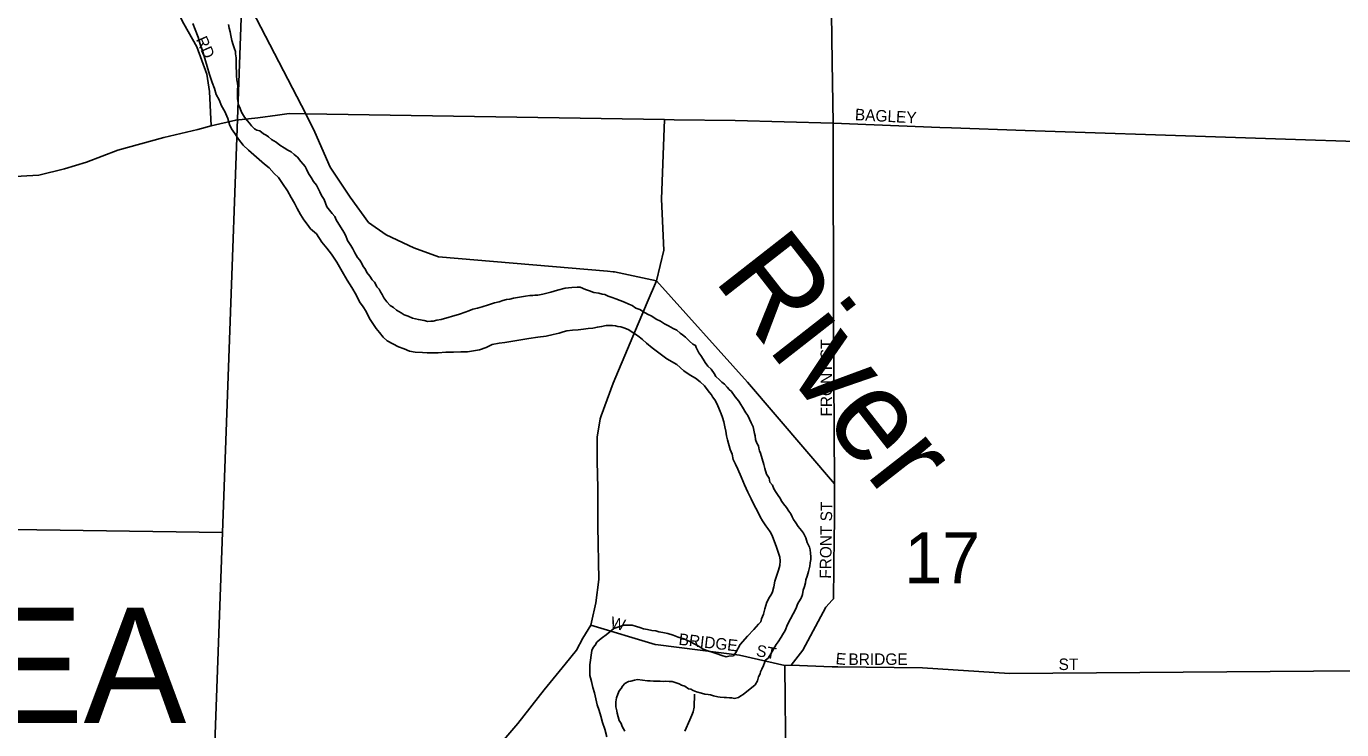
# Model space of a CAD drawing. Extents: x 2010165 to 2382125, y 1060529 to 1407316.
# Drawn here: x 2142658 to 2148360, y 1226696 to 1229747 of the extents above; entities that cross this region are included whole.
import ezdxf

# ---------------------------------------------------------------- set-up
doc = ezdxf.new("R2010")
doc.units = 0
for name, color, linetype in [('GM_X_City_Street', 7, 'Continuous'), ('GM_X_City_Street_Text', 7, 'Continuous'), ('GM_X_Corporation_Text', 7, 'Continuous'), ('GM_X_Major_River', 7, 'Continuous'), ('GM_X_Major_River_Text', 7, 'Continuous'), ('GM_X_Minor_River', 7, 'Continuous'), ('GM_X_Section', 7, 'Continuous'), ('GM_X_Section_Text', 7, 'Continuous'), ('GM_X_State_Route', 7, 'Continuous')]:
    doc.layers.add(name, color=color, linetype=linetype)

msp = doc.modelspace()

# ---------------------------------------------------------------- linework, layer by layer
at = {"layer": 'GM_X_City_Street'}
for points in [[(2143869.2, 1229367.1), (2143460.8, 1230156), (2143301.8, 1230460.3), (2143187.6, 1230770.6), (2143171.3, 1230819.6), (2143165.9, 1230857.7), (2143171.3, 1230890.4), (2143171.3, 1230923), (2143204, 1230966.6), (2143274.8, 1231053.7), (2143911.8, 1231538), (2144293.9, 1231811), (2144500.5, 1231991.2), (2144574.7, 1232072.4), (2144945.5, 1232809), (2146080.9, 1235222.3)], [(2143459.7, 1229315.1), (2143452.4, 1229463.5), (2143439.8, 1229539.5), (2143396.8, 1229657.5), (2143339.9, 1229757.3), (2143285, 1229865.1), (2143238.3, 1229946.9), (2143187.7, 1230020.6), (2143145.2, 1230076.3), (2143017.2, 1230237.5), (2142992.9, 1230257.7), (2142956.4, 1230290.2), (2142903.6, 1230330.8), (2142859, 1230387.6), (2142826.6, 1230432.3), (2142769.8, 1230497.1), (2142673.2, 1230622.5)], [(2141028.6, 1229111.9), (2141449.4, 1229107.7), (2142187.5, 1229094.6), (2142583.5, 1229094.3), (2142711.5, 1229101.5), (2142823.2, 1229128.6), (2142919, 1229157.6), (2143054.6, 1229209), (2143254.1, 1229265), (2143401.8, 1229298.5), (2143459.7, 1229315.1), (2143565.4, 1229340.1), (2143661.4, 1229349.1), (2143747.3, 1229361.9), (2143797.2, 1229368.4), (2143869.2, 1229367.1)], [(2145177.2, 1228684.1), (2144444.4, 1228746.6), (2144338.1, 1228785.7), (2144217.6, 1228842.8), (2144141.2, 1228896.2), (2144062.2, 1229005.8), (2143975.2, 1229135.4), (2143907.9, 1229287.2), (2143869.2, 1229367.1)], [(2143869.2, 1229367.1), (2145423.9, 1229342)], [(2146157.5, 1228440.3), (2146154.9, 1229326.2)], [(2146154.9, 1229326.2), (2146617.4, 1229308.6)], [(2146617.4, 1229308.6), (2146668.8, 1229306.7)], [(2146668.8, 1229306.7), (2146987.2, 1229294.6), (2148724.6, 1229237.6)], [(2145389.1, 1228642.7), (2145207, 1228681.6), (2145201.5, 1228682), (2145177.2, 1228684.1)], [(2146161.3, 1227703.8), (2146161.3, 1227762.9), (2145784.7, 1228202.8), (2145389.1, 1228642.7)], [(2146161.3, 1227762.9), (2146158.1, 1228228.1), (2146157.5, 1228440.3)], [(2146160.5, 1227536.1), (2146161.3, 1227592), (2146161.3, 1227703.8)], [(2146151.2, 1227258.7), (2146156.5, 1227264.5), (2146160.5, 1227536.1)], [(2145973, 1226976.5), (2146023.6, 1227041.4), (2146123.3, 1227228.1), (2146151.2, 1227258.7)], [(2145104.3, 1227149), (2145383.6, 1227065.5), (2145396.2, 1227063.9)], [(2145396.2, 1227063.9), (2145749.9, 1227019.2), (2145946.1, 1226974.9), (2145973, 1226976.5)], [(2146034.9, 1226118.8), (2146028.4, 1226153.7), (2145961.9, 1226419.5), (2145950.8, 1226538.2), (2145946.1, 1226974.9)], [(2145973, 1226976.5), (2146151.8, 1226968.6), (2146176.1, 1226968.3)], [(2146176.1, 1226968.3), (2146542.6, 1226963.9), (2146919.6, 1226940.5), (2148615.5, 1226952.3)]]:
    msp.add_lwpolyline(points, dxfattribs=at)
at = {"layer": 'GM_X_Major_River'}
for points in [[(2144026.4, 1228683.3), (2144003.8, 1228723.2), (2143981.3, 1228759), (2143960.9, 1228784.9), (2143938.6, 1228810.7), (2143916, 1228846.5), (2143889.7, 1228868.3), (2143875.4, 1228888.2), (2143861.2, 1228908.1), (2143846.8, 1228929.9), (2143832.5, 1228955.9), (2143820.1, 1228979.8), (2143805.8, 1229003.7), (2143789.4, 1229033.6), (2143768.9, 1229065.4), (2143750.6, 1229091.3), (2143732.3, 1229109.1), (2143709.9, 1229132.9), (2143689.7, 1229148.7), (2143620.8, 1229210.1), (2143598.4, 1229231.9), (2143578.1, 1229257.7), (2143561.7, 1229281.6), (2143547.4, 1229301.5), (2143539.2, 1229321.4), (2143530.8, 1229347.4), (2143518.4, 1229377.4), (2143504.1, 1229401.3), (2143493.7, 1229427.2), (2143481.4, 1229451.2), (2143473, 1229477.1), (2143462.7, 1229503.1), (2143452.2, 1229537.1), (2143441.7, 1229573.1), (2143431.3, 1229607.1), (2143420.8, 1229641), (2143410.3, 1229673), (2143402, 1229699), (2143389.5, 1229732.9), (2143379.2, 1229758.9)], [(2143533.5, 1229754.8), (2143537.7, 1229738.8), (2143541.9, 1229722.8), (2143544.1, 1229706.8), (2143548.4, 1229684.7), (2143554.7, 1229666.8), (2143560.9, 1229648.8), (2143565.1, 1229636.8), (2143565.2, 1229626.8), (2143567.4, 1229610.7), (2143567.7, 1229590.7), (2143567.8, 1229580.6), (2143568, 1229566.6), (2143568.2, 1229550.5), (2143568.5, 1229532.5), (2143570.7, 1229514.5), (2143572.9, 1229500.4), (2143575.1, 1229486.4), (2143573.3, 1229472.3), (2143573.4, 1229462.3), (2143573.6, 1229444.3), (2143573.8, 1229432.2), (2143578.1, 1229406.2), (2143584.4, 1229390.2), (2143590.6, 1229374.2), (2143602.9, 1229352.3), (2143615.1, 1229338.4), (2143625.3, 1229326.5), (2143633.4, 1229314.6), (2143647.6, 1229302.7), (2143657.7, 1229296.8), (2143669.8, 1229292.9), (2143686, 1229281.1), (2143698.1, 1229275.2), (2143708.2, 1229267.3), (2143720.4, 1229255.4), (2143740.5, 1229243.7), (2143756.7, 1229231.8), (2143774.9, 1229220), (2143791.1, 1229210.2), (2143805.2, 1229202.3), (2143819.4, 1229190.4), (2143833.6, 1229178.6), (2143847.8, 1229160.7), (2143858, 1229148.8), (2143866.1, 1229138.9), (2143872.3, 1229126.9), (2143880.6, 1229108.9), (2143892.8, 1229091), (2143903.1, 1229073.1), (2143915.3, 1229057.2), (2143923.5, 1229043.3), (2143929.7, 1229029.3), (2143937.9, 1229013.3), (2143948.2, 1228995.4), (2143960.6, 1228963.4), (2143983, 1228935.6), (2143995.2, 1228921.7), (2144001.4, 1228907.8), (2144034.2, 1228854), (2144042.4, 1228838), (2144050.7, 1228818.1), (2144065, 1228796.2), (2144073.2, 1228782.2), (2144081.4, 1228764.3), (2144093.7, 1228744.4), (2144103.9, 1228732.5), (2144112.1, 1228718.5), (2144118.3, 1228704.5), (2144126.4, 1228694.6), (2144134.6, 1228678.7), (2144146.9, 1228662.8), (2144157.1, 1228646.8), (2144167.2, 1228636.9), (2144173.4, 1228627), (2144177.5, 1228617), (2144187.7, 1228607.1), (2144193.8, 1228595.1)], [(2145923.9, 1227444.6), (2145909.3, 1227488.5), (2145890.6, 1227538.5), (2145882.4, 1227554.4), (2145872.2, 1227568.3), (2145864, 1227580.3), (2145849.7, 1227602.2), (2145839.5, 1227620.1), (2145827.1, 1227644), (2145812.8, 1227669.9), (2145800.4, 1227697.9), (2145786, 1227725.8), (2145771.6, 1227757.7), (2145757.1, 1227793.6), (2145742.6, 1227825.6), (2145732.3, 1227847.5), (2145722, 1227867.5), (2145717.7, 1227891.5), (2145709.4, 1227911.5), (2145696.9, 1227953.4), (2145692.6, 1227971.4), (2145690.4, 1227991.5), (2145686.1, 1228009.5), (2145681.8, 1228031.5), (2145675.6, 1228049.5), (2145669.4, 1228065.5), (2145663.1, 1228083.4), (2145652.8, 1228107.4), (2145642.5, 1228127.3), (2145632.3, 1228139.2), (2145628.2, 1228149.2), (2145620, 1228159.2), (2145609.9, 1228171.1), (2145597.6, 1228187), (2145579.4, 1228204.8), (2145559.1, 1228220.6), (2145534.9, 1228234.4), (2145508.6, 1228252.1), (2145478.2, 1228279.8), (2145433.8, 1228305.3), (2145399.4, 1228331), (2145371.1, 1228352.7), (2145346.8, 1228372.5), (2145328.5, 1228388.3), (2145314.4, 1228400.2), (2145298.2, 1228412), (2145284, 1228419.9), (2145269.9, 1228429.8), (2145251.8, 1228437.6), (2145235.7, 1228443.4), (2145221.6, 1228445.2), (2145211.6, 1228447.1), (2145199.5, 1228448.9), (2145187.5, 1228448.8), (2145171.5, 1228448.6), (2145151.5, 1228444.3), (2145133.5, 1228442.1), (2145113.5, 1228437.9), (2145093.5, 1228435.6), (2145073.5, 1228433.4), (2145049.5, 1228431.1), (2145025.5, 1228428.8), (2145001.5, 1228426.4), (2144985.5, 1228422.2), (2144967.5, 1228416), (2144941.6, 1228409.7), (2144911.6, 1228403.3), (2144875.6, 1228398.8), (2144835.6, 1228392.3), (2144731.7, 1228375), (2144707.6, 1228372.7), (2144677.7, 1228366.3), (2144651.8, 1228353.9), (2144621.9, 1228343.5), (2144595.9, 1228339.2), (2144569.9, 1228334.9), (2144541.8, 1228334.5), (2144509.8, 1228334.1), (2144475.7, 1228333.7), (2144443.7, 1228331.3), (2144417.7, 1228331), (2144395.6, 1228330.7), (2144375.6, 1228332.5), (2144343.5, 1228334.1), (2144319.4, 1228337.8), (2144295.2, 1228347.6), (2144271.1, 1228357.3), (2144246.9, 1228369), (2144222.7, 1228382.8), (2144204.4, 1228398.6), (2144188.1, 1228418.5), (2144173.9, 1228436.3), (2144159.6, 1228458.2), (2144145.2, 1228480.1), (2144130.8, 1228510.1), (2144118.5, 1228530), (2144102.2, 1228551.8), (2144087.8, 1228581.8), (2144069.4, 1228613.6), (2144048.9, 1228645.5), (2144026.4, 1228683.3)], [(2144193.8, 1228595.1), (2144200, 1228583.1), (2144208.2, 1228569.2), (2144220.5, 1228551.3), (2144234.7, 1228535.4), (2144248.8, 1228527.6), (2144263, 1228515.7), (2144283.2, 1228503.9), (2144295.3, 1228496), (2144313.4, 1228490.2), (2144331.6, 1228480.4), (2144357.7, 1228474.7), (2144381.8, 1228471), (2144397.9, 1228467.2), (2144411.9, 1228467.4), (2144421.9, 1228467.5), (2144437.9, 1228471.7), (2144455.8, 1228475.9), (2144535.7, 1228499), (2144559.6, 1228507.3), (2144575.6, 1228513.5), (2144593.5, 1228519.8), (2144613.5, 1228524), (2144633.5, 1228530.3), (2144661.4, 1228538.6), (2144687.3, 1228547), (2144707.3, 1228551.3), (2144723.3, 1228557.5), (2144739.2, 1228561.7), (2144753.2, 1228563.9), (2144769.2, 1228568.1), (2144795.2, 1228572.4), (2144821.2, 1228576.7), (2144841.2, 1228579), (2144853.2, 1228579.1), (2144863.2, 1228581.3), (2144875.2, 1228581.4), (2144897.2, 1228585.7), (2144931.1, 1228594.1), (2144961.1, 1228602.5), (2144993, 1228610.9), (2145023.1, 1228613.3), (2145045.1, 1228615.6), (2145059.1, 1228615.8), (2145081.2, 1228606), (2145099.4, 1228600.2), (2145117.5, 1228592.4), (2145139.6, 1228588.7), (2145153.7, 1228584.8), (2145165.7, 1228583), (2145179.8, 1228577.1), (2145197.9, 1228571.3), (2145214, 1228565.5), (2145232.2, 1228557.7), (2145250.3, 1228549.9), (2145270.4, 1228542.1), (2145284.5, 1228536.3), (2145300.7, 1228524.4), (2145316.8, 1228518.6), (2145333, 1228508.8), (2145351.1, 1228499), (2145369.3, 1228489.2), (2145387.5, 1228477.3), (2145407.6, 1228467.6), (2145423.8, 1228455.7), (2145442, 1228447.9), (2145452, 1228442), (2145462.1, 1228436.1), (2145478.3, 1228428.3), (2145492.5, 1228416.4), (2145502.6, 1228408.5), (2145514.7, 1228398.6), (2145533, 1228380.8), (2145547.2, 1228368.9), (2145559.3, 1228363.1), (2145561.4, 1228353.1), (2145573.7, 1228331.1), (2145581.9, 1228319.2), (2145592.1, 1228303.3), (2145600.3, 1228289.3), (2145612.5, 1228273.4), (2145626.7, 1228259.6), (2145639, 1228241.7), (2145647.2, 1228227.7), (2145663.4, 1228213.9), (2145673.5, 1228204), (2145683.7, 1228194.1), (2145695.9, 1228182.2), (2145704, 1228172.2), (2145714.2, 1228162.3), (2145730.5, 1228140.4), (2145746.8, 1228120.6), (2145755, 1228106.6), (2145763.1, 1228094.7), (2145777.5, 1228070.8), (2145785.6, 1228058.9), (2145800.1, 1228026.9), (2145808.3, 1228009), (2145814.7, 1227981), (2145816.8, 1227971), (2145819.1, 1227954.9)], [(2145819.1, 1227954.9), (2145825.3, 1227939), (2145831.5, 1227927), (2145833.6, 1227917), (2145835.8, 1227905), (2145839.9, 1227895), (2145854.5, 1227847), (2145858.8, 1227829), (2145867.1, 1227805), (2145877.4, 1227787.1), (2145881.6, 1227769.1), (2145891.8, 1227757.2), (2145898, 1227741.2), (2145908.2, 1227725.3), (2145916.4, 1227711.3), (2145924.6, 1227701.4), (2145932.8, 1227685.5), (2145940.9, 1227675.5), (2145953.2, 1227659.6), (2145963.4, 1227643.7), (2145971.6, 1227631.8), (2145977.7, 1227619.8), (2145983.9, 1227607.8), (2145994.1, 1227593.9), (2146004.3, 1227578), (2146018.6, 1227560.1), (2146026.8, 1227548.2), (2146037, 1227528.2), (2146043.3, 1227508.2), (2146053.6, 1227488.3), (2146055.7, 1227476.3), (2146057.9, 1227462.3), (2146058.1, 1227446.2), (2146058.3, 1227434.2), (2146056.5, 1227420.1), (2146054.7, 1227406.1), (2146050.8, 1227394), (2146049, 1227381.9), (2146043.2, 1227361.8), (2146037.4, 1227345.6), (2146035.6, 1227333.6), (2146031.8, 1227317.5), (2146026, 1227301.3), (2146022.2, 1227283.2), (2146016.4, 1227267.1), (2146006.6, 1227250.9), (2146000.7, 1227240.8), (2145994.9, 1227222.7), (2145957.8, 1227152), (2145948.1, 1227125.8), (2145936.3, 1227107.6), (2145930.5, 1227097.5), (2145916.7, 1227077.3), (2145908.9, 1227065.2), (2145897.1, 1227044.9), (2145885.3, 1227024.7), (2145873.6, 1227006.5), (2145861.6, 1226998.4), (2145853.9, 1226974.2), (2145846.1, 1226958.1), (2145840.3, 1226947.9), (2145838.4, 1226937.9), (2145832.5, 1226925.8), (2145826.8, 1226907.6), (2145817, 1226891.5), (2145765.4, 1226848.7), (2145755.5, 1226842.6), (2145745.6, 1226836.4), (2145727.6, 1226832.2), (2145715.5, 1226834), (2145705.5, 1226833.9), (2145693.5, 1226835.8), (2145683.5, 1226835.7), (2145665.4, 1226837.4), (2145655.4, 1226839.3), (2145637.3, 1226843.1), (2145623.2, 1226846.9), (2145613.2, 1226848.8), (2145599.1, 1226850.7), (2145585, 1226854.5), (2145562.9, 1226860.3), (2145548.8, 1226866.1), (2145538.7, 1226872), (2145528.7, 1226873.9), (2145512.5, 1226885.7), (2145498.4, 1226889.6), (2145488.3, 1226895.5), (2145470.2, 1226901.3), (2145458.2, 1226905.1), (2145444.1, 1226905), (2145430.1, 1226906.8), (2145418.1, 1226904.6), (2145406, 1226906.5), (2145392, 1226906.3), (2145376, 1226906.1), (2145361.9, 1226908), (2145349.9, 1226907.8), (2145307.8, 1226913.3), (2145293.8, 1226911.1), (2145277.8, 1226906.9), (2145267.8, 1226904.8)], [(2145174.8, 1226664.9), (2145166.3, 1226698.9), (2145156, 1226726.8), (2145147.6, 1226754.8), (2145141.2, 1226778.8), (2145132.9, 1226804.8), (2145126.5, 1226830.8), (2145120.2, 1226856.8), (2145113.9, 1226878.8), (2145107.5, 1226904.8), (2145103.3, 1226920.8), (2145101.2, 1226930.8), (2145101, 1226946.9), (2145100.6, 1226977), (2145109.8, 1227039.3), (2145115.6, 1227053.4), (2145123.5, 1227063.5), (2145131.3, 1227075.7), (2145143.2, 1227085.8), (2145155.1, 1227096), (2145171, 1227108.3), (2145186.9, 1227120.5), (2145204.7, 1227134.8), (2145230.6, 1227143.1), (2145248.6, 1227149.3), (2145262.6, 1227149.5), (2145274.6, 1227149.7), (2145284.6, 1227149.8), (2145302.8, 1227144), (2145316.8, 1227140.1), (2145332.9, 1227134.3), (2145351, 1227130.5), (2145369.1, 1227126.8), (2145387.2, 1227125), (2145399.2, 1227121.1), (2145417.3, 1227117.3), (2145439.4, 1227113.6), (2145461.5, 1227105.8), (2145483.7, 1227098.1), (2145507.8, 1227090.3), (2145534, 1227078.6), (2145556.2, 1227066.8), (2145572.3, 1227059), (2145582.4, 1227053.1), (2145592.6, 1227045.2), (2145616.7, 1227037.5), (2145634.8, 1227031.7), (2145652.9, 1227025.9), (2145673.1, 1227018.1), (2145691.2, 1227012.3), (2145703.2, 1227014.5), (2145723.2, 1227016.7), (2145733, 1227030.9), (2145752.6, 1227065.2), (2145784.2, 1227101.8), (2145811.8, 1227130.2), (2145831.6, 1227154.5), (2145841.4, 1227164.6), (2145845.3, 1227176.7), (2145853, 1227196.9), (2145858.7, 1227221), (2145868.4, 1227249.3), (2145880.1, 1227271.5), (2145888, 1227283.6), (2145891.8, 1227293.7), (2145897.6, 1227315.8), (2145903.3, 1227340), (2145910.9, 1227366.2), (2145918.6, 1227388.3), (2145924.4, 1227408.5), (2145926.1, 1227428.5), (2145923.9, 1227444.6)], [(2145267.8, 1226904.8), (2145251.9, 1226896.6), (2145242, 1226884.4), (2145236.2, 1226874.3), (2145228.3, 1226864.2), (2145222.5, 1226850.1), (2145216.7, 1226833.9), (2145212.9, 1226817.8), (2145213.2, 1226795.8), (2145217.4, 1226777.8), (2145219.5, 1226767.8), (2145223.7, 1226751.8), (2145228, 1226735.8), (2145236.1, 1226723.8), (2145240.3, 1226709.8), (2145246.5, 1226699.9), (2145252.6, 1226689.9)]]:
    msp.add_lwpolyline(points, dxfattribs=at)
at = {"layer": 'GM_X_Minor_River'}
msp.add_lwpolyline([(2145555, 1226849.7), (2145553.6, 1226794.1), (2145547.9, 1226773.9), (2145542.1, 1226759.8), (2145534.3, 1226739.7), (2145512.9, 1226689.2)], dxfattribs=at)
at = {"layer": 'GM_X_Section'}
for points in [[(2141648.1, 1230239.3), (2143604.9, 1230220.8), (2143508.2, 1227552.1), (2141594.3, 1227579)], [(2143604.9, 1230220.8), (2146162.4, 1230207.3), (2148785.9, 1230193.6), (2148600.9, 1224775.6), (2143408.8, 1224809.4), (2143508.2, 1227552.1)], [(2143508.2, 1227552.1), (2143408.8, 1224809.4), (2141538.9, 1224835.3), (2141594.3, 1227579)]]:
    msp.add_lwpolyline(points, close=True, dxfattribs=at)
at = {"layer": 'GM_X_State_Route'}
for points in [[(2146151.5, 1229590.7), (2146145.9, 1230013.9)], [(2145466.4, 1229341.6), (2145730.9, 1229338.8), (2146154.9, 1229326.2), (2146151.5, 1229590.7)], [(2145349.6, 1228548.9), (2145389.1, 1228642.7), (2145420.8, 1228775.6), (2145411.3, 1228997.1), (2145423.9, 1229342), (2145466.4, 1229341.6)], [(2145150.4, 1228058.1), (2145202.4, 1228199.6), (2145349.6, 1228548.9)], [(2145107.3, 1227162.3), (2145126.5, 1227247.1), (2145139.1, 1227348.3), (2145135.9, 1227579.3), (2145135.9, 1227743.9), (2145132.8, 1227861), (2145132.8, 1227965.4), (2145145.4, 1228044.5), (2145150.4, 1228058.1)], [(2144194.9, 1225996.6), (2144246.4, 1226062.5), (2144323.3, 1226150), (2144408.4, 1226257.5), (2144517.8, 1226398.8), (2144651.5, 1226562), (2144789.1, 1226723.2), (2144902.6, 1226868.5), (2144993.7, 1226979.9), (2145042.4, 1227041.6), (2145070.9, 1227093.5), (2145104.3, 1227149), (2145107.3, 1227162.3)]]:
    msp.add_lwpolyline(points, dxfattribs=at)

# ---------------------------------------------------------------- texts
at = {"layer": 'GM_X_City_Street_Text'}
for s, rotation, p in [('RD', 293.9648, (2143392, 1229690.1)), ('BAGLEY', 356.9352, (2146248.8, 1229339.8)), ('FRONT ST', 90, (2146150.9, 1228054.4)), ('FRONT ST', 89.1022, (2146146.5, 1227350.6)), ('W', 345.9702, (2145185.8, 1227139.5)), ('BRIDGE', 353.4175, (2145483.8, 1227064.9)), ('ST', 349.3865, (2145818.8, 1227016.4)), ('E', 354.4737, (2146164.5, 1226980.8)), ('BRIDGE', 0, (2146221.9, 1226977)), ('ST', 0, (2147132.7, 1226955))]:
    msp.add_text(s, height=50, rotation=rotation, dxfattribs=at).set_placement(p)
at = {"layer": 'GM_X_Corporation_Text'}
msp.add_text('BEREA', height=500, rotation=0, dxfattribs=at).set_placement((2141084.9, 1226724.8))
at = {"layer": 'GM_X_Major_River_Text'}
msp.add_text('River', height=400.24, rotation=308.0262, dxfattribs=at).set_placement((2145632.8, 1228650.2))
at = {"layer": 'GM_X_Section_Text'}
msp.add_text('17', height=221, rotation=0, dxfattribs=at).set_placement((2146463.9, 1227331.5))

doc.saveas('drawing.dxf')
